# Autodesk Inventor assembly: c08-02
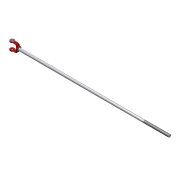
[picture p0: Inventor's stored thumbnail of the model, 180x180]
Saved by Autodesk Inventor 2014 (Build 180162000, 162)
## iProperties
Created: 2010-12
Part Number: c08-02
Document SubType Name: Assembly
Designer: Thom Tremblay
Author: Thom Tremblay
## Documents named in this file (3)
- C:\Inventor 2014 Essentials\Assemblies\Chapter 08\c08-02.iam
- C:\Inventor 2014 Essentials\Parts\Chapter 08\c08-09.ipt
- C:\Inventor 2014 Essentials\Parts\Chapter 08\c08-10.ipt
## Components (2 placed, 2 different names)
1. c08-09:1
2. c08-10:1 — Insert:1
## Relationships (1: Insert 1)
- Insert:1: c08-10:1
